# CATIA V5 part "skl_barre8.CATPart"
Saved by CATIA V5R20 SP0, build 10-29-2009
Part number: skl_barre8
Publications: "Barre_8", "Axe_Pivot_b8b4", "Axe_Pivot_b8b7"
Bounding box of the stored display mesh (mm): x 0 to 394.671, y -170 to 313.648, z 0 to 20
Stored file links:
  C:\Users\Matthieu\Desktop\IFMA\Cours 2A\Thinkmotion\skl_barre8.CATPart
  C:\Users\Matthieu\Desktop\IFMA\Cours 2A\Thinkmotion\skl_IAO_bis.CATProduct
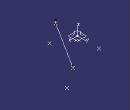
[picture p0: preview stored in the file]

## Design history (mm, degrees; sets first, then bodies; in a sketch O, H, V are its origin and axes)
AxisSystem1: origin (0, 0, 0), X (1, 0, 0), Y (0, 1, 0), Z (0, 0, 1)
Set1
  Point1 "Point.N": linked copy from another document
  Point2 "Point.E": linked copy from another document
  Point3 "Point.L": linked copy from another document
  Point4 "Point.H": linked copy from another document
  Point5 "Point.K": linked copy from another document
  Plane1 "Plan_Ref": linked copy from another document
Body1 (main body)
  Line1 "Barre_8": type PtPt, FirstPoint Point1, SecondPoint Point2
  Line2 "Axe_Pivot_b8b4": type Normal, RefPoint Point2, RefSkin Plane1, Start 0, End 20
  Line3 "Axe_Pivot_b8b7": type Normal, RefPoint Point1, RefSkin Plane1, Start 0, End 20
